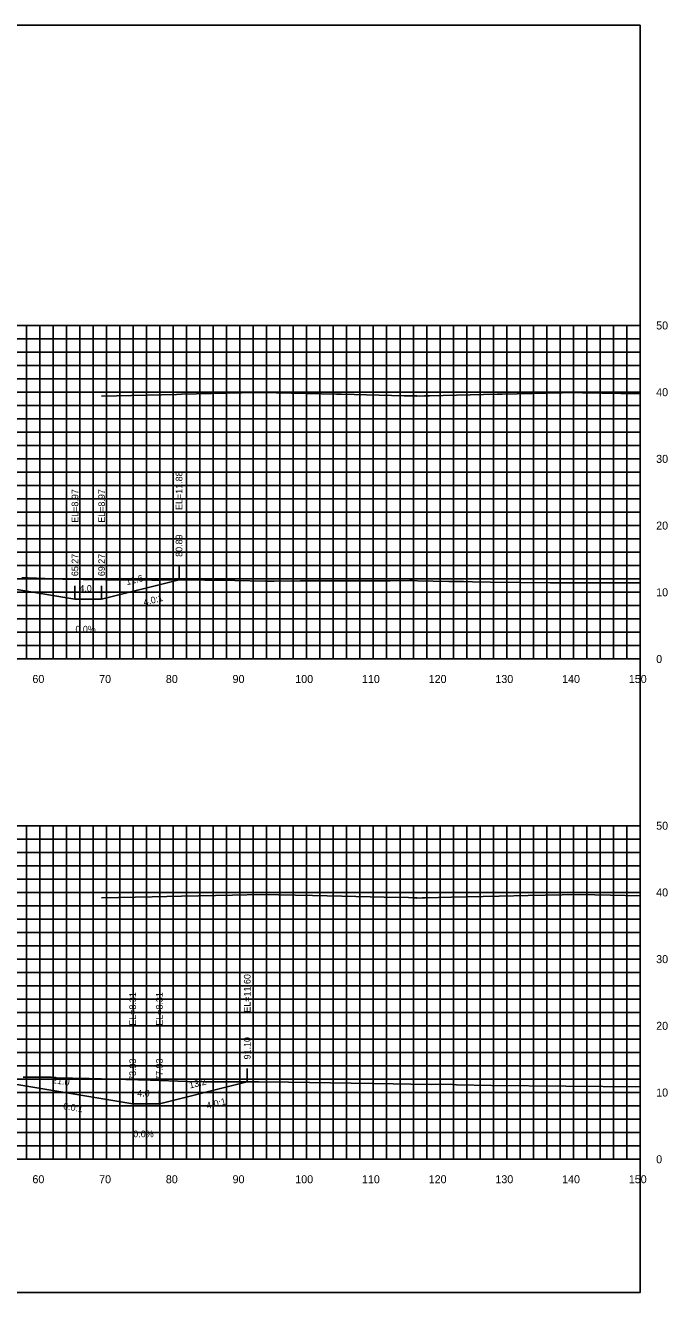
# Model space of a CAD drawing. Extents: x 1797714 to 1804825, y 249015 to 250269.
# Drawn here: x 1802322 to 1802418.3, y 249628.2 to 249818.2 of the extents above; entities that cross this region are included whole.
import ezdxf

# ---------------------------------------------------------------- set-up
doc = ezdxf.new("R2010")
doc.units = 0
for name, color, linetype in [('10', 7, 'Continuous'), ('3', 7, 'Continuous'), ('31', 7, 'Continuous'), ('4', 7, 'Continuous'), ('60', 7, 'Continuous'), ('CL-CNST', 7, 'Continuous'), ('Level 62', 7, 'Continuous'), ('M-ROADS', 7, 'Continuous')]:
    doc.layers.add(name, color=color, linetype=linetype)

msp = doc.modelspace()

# ---------------------------------------------------------------- linework, layer by layer
for p, q in [((1802345.04, 249735.04), (1802345.04, 249737.04)), ((1802329.43, 249732.14), (1802329.43, 249734.14)), ((1802333.43, 249732.14), (1802333.43, 249734.14)), ((1802355.26, 249659.77), (1802355.26, 249661.77)), ((1802338.09, 249656.47), (1802338.09, 249658.47)), ((1802342.09, 249656.47), (1802342.09, 249658.47))]:
    msp.add_line(p, q)
msp.add_lwpolyline([(1802114.16, 249628.17), (1802414.16, 249628.17), (1802414.16, 249818.17), (1802114.16, 249818.17)], close=True)
at = {"layer": '60'}
for p, q in [((1802414.16, 249723.17), (1802414.16, 249773.17)), ((1802414.22, 249773.17), (1802414.16, 249773.17)), ((1802414.22, 249763.17), (1802414.16, 249763.17)), ((1802414.22, 249753.17), (1802414.16, 249753.17)), ((1802414.22, 249743.17), (1802414.16, 249743.17)), ((1802414.22, 249733.17), (1802414.16, 249733.17)), ((1802114.16, 249723.17), (1802414.16, 249723.17)), ((1802324.16, 249723.11), (1802324.16, 249723.17)), ((1802334.16, 249723.11), (1802334.16, 249723.17)), ((1802344.16, 249723.11), (1802344.16, 249723.17)), ((1802354.16, 249723.11), (1802354.16, 249723.17)), ((1802364.16, 249723.11), (1802364.16, 249723.17)), ((1802374.16, 249723.11), (1802374.16, 249723.17)), ((1802384.16, 249723.11), (1802384.16, 249723.17)), ((1802394.16, 249723.11), (1802394.16, 249723.17)), ((1802404.16, 249723.11), (1802404.16, 249723.17)), ((1802414.16, 249723.11), (1802414.16, 249723.17)), ((1802414.22, 249723.17), (1802414.16, 249723.17)), ((1802414.16, 249648.17), (1802414.16, 249698.17)), ((1802414.22, 249698.17), (1802414.16, 249698.17)), ((1802414.22, 249688.17), (1802414.16, 249688.17)), ((1802414.22, 249678.17), (1802414.16, 249678.17)), ((1802414.22, 249668.17), (1802414.16, 249668.17)), ((1802414.22, 249658.17), (1802414.16, 249658.17)), ((1802114.16, 249648.17), (1802414.16, 249648.17)), ((1802324.16, 249648.11), (1802324.16, 249648.17)), ((1802334.16, 249648.11), (1802334.16, 249648.17)), ((1802344.16, 249648.11), (1802344.16, 249648.17)), ((1802354.16, 249648.11), (1802354.16, 249648.17)), ((1802364.16, 249648.11), (1802364.16, 249648.17)), ((1802374.16, 249648.11), (1802374.16, 249648.17)), ((1802384.16, 249648.11), (1802384.16, 249648.17)), ((1802394.16, 249648.11), (1802394.16, 249648.17)), ((1802404.16, 249648.11), (1802404.16, 249648.17)), ((1802414.16, 249648.11), (1802414.16, 249648.17)), ((1802414.22, 249648.17), (1802414.16, 249648.17))]:
    msp.add_line(p, q, dxfattribs=at)
at = {"layer": 'CL-CNST'}
for points in [[(1802333.41, 249762.58), (1802344.65, 249762.83), (1802345.41, 249762.85), (1802356.66, 249763.1), (1802357.41, 249763.11), (1802368.66, 249762.86), (1802369.41, 249762.85), (1802378.79, 249762.64), (1802379.41, 249762.63), (1802380.58, 249762.6), (1802380.66, 249762.6), (1802380.66, 249762.58), (1802380.66, 249762.58), (1802381.83, 249762.61), (1802381.91, 249762.61), (1802382.56, 249762.62), (1802392.72, 249762.85), (1802393.47, 249762.86), (1802404.72, 249763.11), (1802405.5, 249763.09), (1802414.16, 249762.9)], [(1802226.17, 249736.26), (1802229.08, 249737.23), (1802230.08, 249737.19), (1802240.08, 249737.04), (1802245.91, 249736.8), (1802246.24, 249736.8), (1802246.4, 249736.3), (1802248.4, 249736.46), (1802264.16, 249736.81), (1802297.35, 249736.08), (1802301.35, 249735.92), (1802308.43, 249735.64), (1802329.43, 249732.14), (1802333.43, 249732.14), (1802345.04, 249735.04)], [(1802333.42, 249687.34), (1802341.03, 249687.51), (1802345.42, 249687.61), (1802353.03, 249687.77), (1802357.42, 249687.87), (1802365.04, 249687.7), (1802369.42, 249687.61), (1802375.77, 249687.47), (1802379.42, 249687.39), (1802380.21, 249687.37), (1802380.66, 249687.36), (1802380.67, 249687.34), (1802380.67, 249687.33), (1802381.46, 249687.35), (1802381.92, 249687.36), (1802385.87, 249687.45), (1802393.01, 249687.61), (1802397.38, 249687.7), (1802405.01, 249687.87), (1802409.69, 249687.77), (1802414.16, 249687.67)], [(1802215.79, 249660.73), (1802217.62, 249661.34), (1802218.62, 249661.3), (1802228.62, 249661.15), (1802233.28, 249660.96), (1802233.61, 249660.96), (1802233.77, 249660.46), (1802235.77, 249660.62), (1802264.16, 249661.25), (1802311.09, 249660.21), (1802315.09, 249660.05), (1802317.09, 249659.97), (1802338.09, 249656.47), (1802342.09, 249656.47), (1802355.26, 249659.77)]]:
    msp.add_lwpolyline(points, dxfattribs=at)
at = {"layer": 'Level 62'}
for p, q in [((1802114.16, 249773.17), (1802414.16, 249773.17)), ((1802322.16, 249723.17), (1802322.16, 249773.17)), ((1802324.16, 249723.17), (1802324.16, 249773.17)), ((1802326.16, 249723.17), (1802326.16, 249773.17)), ((1802328.16, 249723.17), (1802328.16, 249773.17)), ((1802330.16, 249723.17), (1802330.16, 249773.17)), ((1802332.16, 249723.17), (1802332.16, 249773.17)), ((1802334.16, 249723.17), (1802334.16, 249773.17)), ((1802336.16, 249723.17), (1802336.16, 249773.17)), ((1802338.16, 249723.17), (1802338.16, 249773.17)), ((1802340.16, 249723.17), (1802340.16, 249773.17)), ((1802342.16, 249723.17), (1802342.16, 249773.17)), ((1802344.16, 249723.17), (1802344.16, 249773.17)), ((1802346.16, 249723.17), (1802346.16, 249773.17)), ((1802348.16, 249723.17), (1802348.16, 249773.17)), ((1802350.16, 249723.17), (1802350.16, 249773.17)), ((1802352.16, 249723.17), (1802352.16, 249773.17)), ((1802354.16, 249723.17), (1802354.16, 249773.17)), ((1802356.16, 249723.17), (1802356.16, 249773.17)), ((1802358.16, 249723.17), (1802358.16, 249773.17)), ((1802360.16, 249723.17), (1802360.16, 249773.17)), ((1802362.16, 249723.17), (1802362.16, 249773.17)), ((1802364.16, 249723.17), (1802364.16, 249773.17)), ((1802366.16, 249723.17), (1802366.16, 249773.17)), ((1802368.16, 249723.17), (1802368.16, 249773.17)), ((1802370.16, 249723.17), (1802370.16, 249773.17)), ((1802372.16, 249723.17), (1802372.16, 249773.17)), ((1802374.16, 249723.17), (1802374.16, 249773.17)), ((1802376.16, 249723.17), (1802376.16, 249773.17)), ((1802378.16, 249723.17), (1802378.16, 249773.17)), ((1802380.16, 249723.17), (1802380.16, 249773.17)), ((1802382.16, 249723.17), (1802382.16, 249773.17)), ((1802384.16, 249723.17), (1802384.16, 249773.17)), ((1802386.16, 249723.17), (1802386.16, 249773.17)), ((1802388.16, 249723.17), (1802388.16, 249773.17)), ((1802390.16, 249723.17), (1802390.16, 249773.17)), ((1802392.16, 249723.17), (1802392.16, 249773.17)), ((1802394.16, 249723.17), (1802394.16, 249773.17)), ((1802396.16, 249723.17), (1802396.16, 249773.17)), ((1802398.16, 249723.17), (1802398.16, 249773.17)), ((1802400.16, 249723.17), (1802400.16, 249773.17)), ((1802402.16, 249723.17), (1802402.16, 249773.17)), ((1802404.16, 249723.17), (1802404.16, 249773.17)), ((1802406.16, 249723.17), (1802406.16, 249773.17)), ((1802408.16, 249723.17), (1802408.16, 249773.17)), ((1802410.16, 249723.17), (1802410.16, 249773.17)), ((1802412.16, 249723.17), (1802412.16, 249773.17)), ((1802414.16, 249723.17), (1802414.16, 249773.17)), ((1802114.16, 249771.17), (1802414.16, 249771.17)), ((1802114.16, 249769.17), (1802414.16, 249769.17)), ((1802114.16, 249767.17), (1802414.16, 249767.17)), ((1802114.16, 249765.17), (1802414.16, 249765.17)), ((1802114.16, 249763.17), (1802414.16, 249763.17)), ((1802114.16, 249761.17), (1802414.16, 249761.17)), ((1802114.16, 249759.17), (1802414.16, 249759.17)), ((1802114.16, 249757.17), (1802414.16, 249757.17)), ((1802114.16, 249755.17), (1802414.16, 249755.17)), ((1802114.16, 249753.17), (1802414.16, 249753.17)), ((1802114.16, 249751.17), (1802414.16, 249751.17)), ((1802114.16, 249749.17), (1802414.16, 249749.17)), ((1802114.16, 249747.17), (1802414.16, 249747.17)), ((1802114.16, 249745.17), (1802414.16, 249745.17)), ((1802114.16, 249743.17), (1802414.16, 249743.17)), ((1802114.16, 249741.17), (1802414.16, 249741.17)), ((1802114.16, 249739.17), (1802414.16, 249739.17)), ((1802114.16, 249737.17), (1802414.16, 249737.17)), ((1802114.16, 249735.17), (1802414.16, 249735.17)), ((1802114.16, 249733.17), (1802414.16, 249733.17)), ((1802114.16, 249731.17), (1802414.16, 249731.17)), ((1802114.16, 249729.17), (1802414.16, 249729.17)), ((1802114.16, 249727.17), (1802414.16, 249727.17)), ((1802114.16, 249725.17), (1802414.16, 249725.17)), ((1802114.16, 249723.17), (1802414.16, 249723.17)), ((1802114.16, 249698.17), (1802414.16, 249698.17)), ((1802322.16, 249648.17), (1802322.16, 249698.17)), ((1802324.16, 249648.17), (1802324.16, 249698.17)), ((1802326.16, 249648.17), (1802326.16, 249698.17)), ((1802328.16, 249648.17), (1802328.16, 249698.17)), ((1802330.16, 249648.17), (1802330.16, 249698.17)), ((1802332.16, 249648.17), (1802332.16, 249698.17)), ((1802334.16, 249648.17), (1802334.16, 249698.17)), ((1802336.16, 249648.17), (1802336.16, 249698.17)), ((1802338.16, 249648.17), (1802338.16, 249698.17)), ((1802340.16, 249648.17), (1802340.16, 249698.17)), ((1802342.16, 249648.17), (1802342.16, 249698.17)), ((1802344.16, 249648.17), (1802344.16, 249698.17)), ((1802346.16, 249648.17), (1802346.16, 249698.17)), ((1802348.16, 249648.17), (1802348.16, 249698.17)), ((1802350.16, 249648.17), (1802350.16, 249698.17)), ((1802352.16, 249648.17), (1802352.16, 249698.17)), ((1802354.16, 249648.17), (1802354.16, 249698.17)), ((1802356.16, 249648.17), (1802356.16, 249698.17)), ((1802358.16, 249648.17), (1802358.16, 249698.17)), ((1802360.16, 249648.17), (1802360.16, 249698.17)), ((1802362.16, 249648.17), (1802362.16, 249698.17)), ((1802364.16, 249648.17), (1802364.16, 249698.17)), ((1802366.16, 249648.17), (1802366.16, 249698.17)), ((1802368.16, 249648.17), (1802368.16, 249698.17)), ((1802370.16, 249648.17), (1802370.16, 249698.17)), ((1802372.16, 249648.17), (1802372.16, 249698.17)), ((1802374.16, 249648.17), (1802374.16, 249698.17)), ((1802376.16, 249648.17), (1802376.16, 249698.17)), ((1802378.16, 249648.17), (1802378.16, 249698.17)), ((1802380.16, 249648.17), (1802380.16, 249698.17)), ((1802382.16, 249648.17), (1802382.16, 249698.17)), ((1802384.16, 249648.17), (1802384.16, 249698.17)), ((1802386.16, 249648.17), (1802386.16, 249698.17)), ((1802388.16, 249648.17), (1802388.16, 249698.17)), ((1802390.16, 249648.17), (1802390.16, 249698.17)), ((1802392.16, 249648.17), (1802392.16, 249698.17)), ((1802394.16, 249648.17), (1802394.16, 249698.17)), ((1802396.16, 249648.17), (1802396.16, 249698.17)), ((1802398.16, 249648.17), (1802398.16, 249698.17)), ((1802400.16, 249648.17), (1802400.16, 249698.17)), ((1802402.16, 249648.17), (1802402.16, 249698.17)), ((1802404.16, 249648.17), (1802404.16, 249698.17)), ((1802406.16, 249648.17), (1802406.16, 249698.17)), ((1802408.16, 249648.17), (1802408.16, 249698.17)), ((1802410.16, 249648.17), (1802410.16, 249698.17)), ((1802412.16, 249648.17), (1802412.16, 249698.17)), ((1802414.16, 249648.17), (1802414.16, 249698.17)), ((1802114.16, 249696.17), (1802414.16, 249696.17)), ((1802114.16, 249694.17), (1802414.16, 249694.17)), ((1802114.16, 249692.17), (1802414.16, 249692.17)), ((1802114.16, 249690.17), (1802414.16, 249690.17)), ((1802114.16, 249688.17), (1802414.16, 249688.17)), ((1802114.16, 249686.17), (1802414.16, 249686.17)), ((1802114.16, 249684.17), (1802414.16, 249684.17)), ((1802114.16, 249682.17), (1802414.16, 249682.17)), ((1802114.16, 249680.17), (1802414.16, 249680.17)), ((1802114.16, 249678.17), (1802414.16, 249678.17)), ((1802114.16, 249676.17), (1802414.16, 249676.17)), ((1802114.16, 249674.17), (1802414.16, 249674.17)), ((1802114.16, 249672.17), (1802414.16, 249672.17)), ((1802114.16, 249670.17), (1802414.16, 249670.17)), ((1802114.16, 249668.17), (1802414.16, 249668.17)), ((1802114.16, 249666.17), (1802414.16, 249666.17)), ((1802114.16, 249664.17), (1802414.16, 249664.17)), ((1802114.16, 249662.17), (1802414.16, 249662.17)), ((1802114.16, 249660.17), (1802414.16, 249660.17)), ((1802114.16, 249658.17), (1802414.16, 249658.17)), ((1802114.16, 249656.17), (1802414.16, 249656.17)), ((1802114.16, 249654.17), (1802414.16, 249654.17)), ((1802114.16, 249652.17), (1802414.16, 249652.17)), ((1802114.16, 249650.17), (1802414.16, 249650.17)), ((1802114.16, 249648.17), (1802414.16, 249648.17))]:
    msp.add_line(p, q, dxfattribs=at)
at = {"layer": 'M-ROADS'}
for points in [[(1802321.47, 249735.35), (1802322.38, 249735.35), (1802327.64, 249735.15), (1802330.73, 249735.1), (1802334.01, 249735.04), (1802340.98, 249734.99), (1802342.17, 249735.01), (1802344.36, 249735.05), (1802353.4, 249734.95), (1802357.98, 249734.84), (1802358.29, 249734.84), (1802359.1, 249734.83), (1802359.29, 249734.83), (1802363.25, 249734.89), (1802370.7, 249734.89), (1802376.67, 249734.9), (1802379.56, 249734.95), (1802379.86, 249734.95), (1802379.92, 249734.95), (1802380.13, 249734.95), (1802380.77, 249734.91), (1802385.48, 249734.79), (1802386.62, 249734.79), (1802386.86, 249734.79), (1802387.69, 249734.79), (1802389.02, 249734.76), (1802391.75, 249734.71), (1802400.68, 249734.57), (1802414.16, 249734.59)], [(1802321.69, 249660.45), (1802323.18, 249660.45), (1802323.49, 249660.45), (1802324.58, 249660.45), (1802325.87, 249660.45), (1802326.61, 249660.35), (1802331.58, 249660.29), (1802340.78, 249660.02), (1802346.23, 249659.8), (1802348.83, 249659.79), (1802349.55, 249659.79), (1802349.76, 249659.79), (1802350.76, 249659.79), (1802352.97, 249659.79), (1802356.98, 249659.75), (1802361.47, 249659.72), (1802377.14, 249659.49), (1802379.8, 249659.4), (1802382.86, 249659.36), (1802384.37, 249659.41), (1802386.16, 249659.36), (1802386.61, 249659.31), (1802391.88, 249659.2), (1802414.16, 249659.01)]]:
    msp.add_lwpolyline(points, dxfattribs=at)

# ---------------------------------------------------------------- texts
for s, rotation, p in [('4.0:1', 14.0362, (1802339.84, 249731.17)), ('-6.0:1', 350.5377, (1802327.18, 249655.76)), ('4.0:1', 14.0362, (1802349.28, 249655.69))]:
    msp.add_text(s, height=1, rotation=rotation).set_placement(p)
at = {"layer": '10'}
for s, p in [('60', (1802323.06, 249719.57)), ('70', (1802333.06, 249719.57)), ('80', (1802343.06, 249719.57)), ('90', (1802353.06, 249719.57)), ('100', (1802362.46, 249719.57)), ('110', (1802372.46, 249719.57)), ('120', (1802382.46, 249719.57)), ('130', (1802392.46, 249719.57)), ('140', (1802402.46, 249719.57)), ('150', (1802412.46, 249719.57)), ('60', (1802323.06, 249644.57)), ('70', (1802333.06, 249644.57)), ('80', (1802343.06, 249644.57)), ('90', (1802353.06, 249644.57)), ('100', (1802362.46, 249644.57)), ('110', (1802372.46, 249644.57)), ('120', (1802382.46, 249644.57)), ('130', (1802392.46, 249644.57)), ('140', (1802402.46, 249644.57)), ('150', (1802412.46, 249644.57))]:
    msp.add_text(s, height=1.2, dxfattribs=at).set_placement(p)
at = {"layer": '3'}
for s, p in [('EL=11.88', (1802345.54, 249745.52)), ('EL=8.97', (1802329.93, 249743.6)), ('EL=8.97', (1802333.93, 249743.6)), ('80.89', (1802345.54, 249738.49)), ('65.27', (1802329.93, 249735.59)), ('69.27', (1802333.93, 249735.59)), ('EL=11.60', (1802355.76, 249670.16)), ('EL=8.31', (1802338.59, 249668.19)), ('EL=8.31', (1802342.59, 249668.19)), ('91.10', (1802355.76, 249663.14)), ('73.93', (1802338.59, 249659.92)), ('77.93', (1802342.59, 249659.92))]:
    msp.add_text(s, height=1, rotation=90, dxfattribs=at).set_placement(p)
at = {"layer": '31'}
for s, p in [('50', (1802416.56, 249772.57)), ('40', (1802416.56, 249762.57)), ('30', (1802416.56, 249752.57)), ('20', (1802416.56, 249742.57)), ('10', (1802416.56, 249732.57)), ('0', (1802416.56, 249722.57)), ('50', (1802416.56, 249697.57)), ('40', (1802416.56, 249687.57)), ('30', (1802416.56, 249677.57)), ('20', (1802416.56, 249667.57)), ('10', (1802416.56, 249657.57)), ('0', (1802416.56, 249647.57))]:
    msp.add_text(s, height=1.2, dxfattribs=at).set_placement(p)
at = {"layer": '4'}
for s, p in [('4.0', (1802330.1, 249733.24)), ('0.0%', (1802329.51, 249727.14)), ('4.0', (1802338.77, 249657.57)), ('0.0%', (1802338.18, 249651.47))]:
    msp.add_text(s, height=1, dxfattribs=at).set_placement(p)
for s, rotation, p in [('11.6', 14.0362, (1802337.22, 249734.22)), ('21.0', 350.5377, (1802325.98, 249659.61)), ('13.2', 14.0362, (1802346.68, 249658.76))]:
    msp.add_text(s, height=1, rotation=rotation, dxfattribs=at).set_placement(p)

doc.saveas('drawing.dxf')
